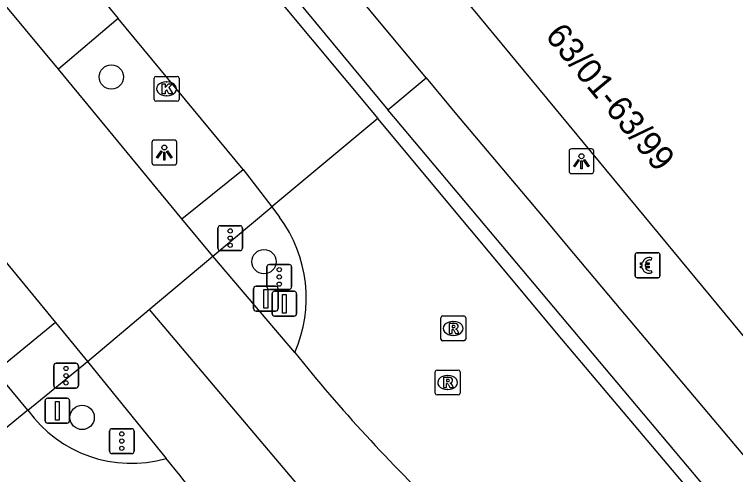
# Model space of a CAD drawing. Extents: x 159489 to 160304, y 383826 to 384530.
# Drawn here: x 160033.79 to 160062.78, y 384172.02 to 384190.51 of the extents above; entities that cross this region are included whole.
import ezdxf

# ---------------------------------------------------------------- set-up
doc = ezdxf.new("R2010")
doc.units = 0
for name, color, linetype in [('IMGEO_Berm_open', 7, 'Continuous'), ('IMGEO_Betaalautomaat', 7, 'Continuous'), ('IMGEO_Boom', 7, 'Continuous'), ('IMGEO_Fietspad_open', 7, 'Continuous'), ('IMGEO_Kolk', 7, 'Continuous'), ('IMGEO_Lichtpunt', 7, 'Continuous'), ('IMGEO_OVBaan_gesloten', 7, 'Continuous'), ('IMGEO_Pand', 7, 'Continuous'), ('IMGEO_Pand_nummerreeks', 7, 'Continuous'), ('IMGEO_Rijbaan_lokaal_gesloten', 7, 'Continuous'), ('IMGEO_Rioolput', 7, 'Continuous'), ('IMGEO_Verkeersbordpaal', 7, 'Continuous'), ('IMGEO_Verkeersregelinstallatiepaal', 7, 'Continuous'), ('IMGEO_Voetpad_open', 7, 'Continuous')]:
    doc.layers.add(name, color=color, linetype=linetype)

msp = doc.modelspace()

# ---------------------------------------------------------------- linework, layer by layer
at = {"layer": 'IMGEO_Berm_open'}
msp.add_lwpolyline([(160037.958, 384190.34), (160035.565, 384188.31)], dxfattribs=at)
at = {"layer": 'IMGEO_Betaalautomaat'}
for p, q in [((160058.815, 384180.926), (160059.656, 384180.926)), ((160059.656, 384180.926), (160058.815, 384180.926)), ((160058.74, 384180.002), (160058.74, 384180.843)), ((160058.74, 384180.843), (160058.74, 384180.002)), ((160059.402, 384180.731), (160059.385, 384180.631)), ((160059.739, 384180.852), (160059.739, 384180.011)), ((160059.739, 384180.011), (160059.739, 384180.852)), ((160059.023, 384180.39), (160059.023, 384180.458)), ((160059.144, 384180.458), (160059.144, 384180.39)), ((160059.389, 384180.225), (160059.411, 384180.138)), ((160059.665, 384179.927), (160058.824, 384179.927)), ((160058.824, 384179.927), (160059.665, 384179.927))]:
    msp.add_line(p, q, dxfattribs=at)
for points in [[(160059.023, 384180.458), (160058.954, 384180.458), (160058.954, 384180.527), (160059.033, 384180.527)], [(160059.028, 384180.321), (160058.954, 384180.321), (160058.954, 384180.39), (160059.023, 384180.39)], [(160059.155, 384180.527), (160059.302, 384180.527), (160059.302, 384180.458), (160059.144, 384180.458)], [(160059.144, 384180.39), (160059.302, 384180.39), (160059.302, 384180.321), (160059.158, 384180.321)]]:
    msp.add_lwpolyline(points, dxfattribs=at)
for centre, radius, start, end in [((160058.818, 384180.849), 0.0779, 92.4484, 184.2845), ((160058.818, 384180.849), 0.0779, 92.4484, 184.2845), ((160059.662, 384180.849), 0.0779, 2.4484, 94.2845), ((160059.662, 384180.849), 0.0779, 2.4484, 94.2845), ((160059.316, 384180.451), 0.293, 73.014, 165.0139), ((160059.322, 384180.464), 0.179, 69.3236, 159.5683), ((160059.289, 384180.376), 0.267, 191.8096, 297.0389), ((160059.322, 384180.391), 0.179, 202.7625, 291.8693), ((160058.818, 384180.005), 0.0779, 182.4484, 274.2845), ((160058.818, 384180.005), 0.0779, 182.4484, 274.2845), ((160059.662, 384180.005), 0.0779, 272.4484, 4.2845), ((160059.662, 384180.005), 0.0779, 272.4484, 4.2845)]:
    msp.add_arc(centre, radius, start, end, dxfattribs=at)
at = {"layer": 'IMGEO_Boom'}
for centre in [(160037.683, 384187.997), (160043.821, 384180.573), (160036.511, 384174.315)]:
    msp.add_circle(centre, 0.489, dxfattribs=at)
at = {"layer": 'IMGEO_Fietspad_open'}
for points in [[(160040.522, 384182.292), (160042.981, 384184.276)], [(160041.761, 384180.79), (160044.135, 384182.772)], [(160035.438, 384178.135), (160033.026, 384176.155)], [(160034.331, 384174.603), (160036.725, 384176.568)]]:
    msp.add_lwpolyline(points, dxfattribs=at)
at = {"layer": 'IMGEO_Kolk'}
for p, q in [((160039.405, 384187.093), (160039.405, 384187.945)), ((160039.48, 384188.019), (160040.332, 384188.019)), ((160040.406, 384187.945), (160040.406, 384187.093)), ((160039.893, 384187.799), (160039.918, 384187.799)), ((160040.332, 384187.019), (160039.48, 384187.019)), ((160039.916, 384187.239), (160039.891, 384187.239))]:
    msp.add_line(p, q, dxfattribs=at)
for points in [[(160039.405, 384187.093), (160039.405, 384187.945)], [(160039.48, 384188.019), (160040.332, 384188.019)], [(160040.406, 384187.945), (160040.406, 384187.093)], [(160039.726, 384187.719), (160039.849, 384187.719), (160039.849, 384187.568), (160039.979, 384187.719), (160040.143, 384187.719), (160039.997, 384187.568), (160040.15, 384187.319), (160039.998, 384187.319), (160039.913, 384187.483), (160039.849, 384187.416), (160039.849, 384187.319), (160039.726, 384187.319), (160039.726, 384187.719)], [(160040.332, 384187.019), (160039.48, 384187.019)]]:
    msp.add_lwpolyline(points, dxfattribs=at)
for centre, start, end in [((160039.482, 384187.943), 91.552, 178.448), ((160039.482, 384187.943), 91.552, 178.448), ((160040.33, 384187.943), 1.552, 88.448), ((160040.33, 384187.943), 1.552, 88.448), ((160039.482, 384187.095), 181.552, 268.448), ((160039.482, 384187.095), 181.552, 268.448), ((160040.33, 384187.095), 271.552, 358.448), ((160040.33, 384187.095), 271.552, 358.448)]:
    msp.add_arc(centre, 0.0765, start, end, dxfattribs=at)
for centre, major_axis, ratio, start_param, end_param in [((160039.892, 384187.519), (-0.387, 0.002), 0.722429, 4.712389, 7.853982), ((160039.917, 384187.519), (-0.39, 0.002), 0.717154, 1.570796, 4.712389)]:
    msp.add_ellipse(centre, major_axis=major_axis, ratio=ratio, start_param=start_param, end_param=end_param, dxfattribs=at)
at = {"layer": 'IMGEO_Lichtpunt'}
for p, q in [((160039.317, 384185.363), (160039.317, 384184.556)), ((160039.317, 384185.363), (160039.317, 384184.556)), ((160040.219, 384185.458), (160039.411, 384185.458)), ((160040.219, 384185.458), (160039.411, 384185.458)), ((160040.313, 384184.556), (160040.313, 384185.363)), ((160040.313, 384184.556), (160040.313, 384185.363)), ((160056.084, 384185.014), (160056.084, 384184.207)), ((160056.084, 384185.014), (160056.084, 384184.207)), ((160056.986, 384185.109), (160056.178, 384185.109)), ((160056.986, 384185.109), (160056.178, 384185.109)), ((160057.08, 384184.207), (160057.08, 384185.014)), ((160057.08, 384184.207), (160057.08, 384185.014)), ((160039.411, 384184.462), (160040.219, 384184.462)), ((160039.411, 384184.462), (160040.219, 384184.462)), ((160056.178, 384184.113), (160056.986, 384184.113)), ((160056.178, 384184.113), (160056.986, 384184.113))]:
    msp.add_line(p, q, dxfattribs=at)
for points in [[(160039.691, 384185.027), (160039.73, 384184.999), (160039.542, 384184.737), (160039.504, 384184.764), (160039.691, 384185.027)], [(160039.793, 384184.979), (160039.84, 384184.979), (160039.84, 384184.657), (160039.793, 384184.657), (160039.793, 384184.979)], [(160039.903, 384184.999), (160039.941, 384185.026), (160040.128, 384184.764), (160040.089, 384184.736), (160039.903, 384184.999)], [(160056.458, 384184.678), (160056.497, 384184.65), (160056.309, 384184.388), (160056.271, 384184.415), (160056.458, 384184.678)], [(160056.67, 384184.65), (160056.708, 384184.677), (160056.895, 384184.415), (160056.856, 384184.387), (160056.67, 384184.65)], [(160056.56, 384184.63), (160056.607, 384184.63), (160056.607, 384184.308), (160056.56, 384184.308), (160056.56, 384184.63)]]:
    msp.add_lwpolyline(points, dxfattribs=at)
for centre in [(160039.816, 384185.161), (160056.583, 384184.812)]:
    msp.add_circle(centre, 0.0994, dxfattribs=at)
for centre, start, end in [((160039.411, 384185.363), 90, 180), ((160039.411, 384185.363), 90, 180), ((160040.219, 384185.363), 0, 90), ((160040.219, 384185.363), 0, 90), ((160056.178, 384185.014), 90, 180), ((160056.178, 384185.014), 90, 180), ((160056.986, 384185.014), 0, 90), ((160056.986, 384185.014), 0, 90), ((160039.411, 384184.556), 180, 270), ((160039.411, 384184.556), 180, 270), ((160040.219, 384184.556), 270, 0), ((160040.219, 384184.556), 270, 360), ((160056.178, 384184.207), 180, 270), ((160056.178, 384184.207), 180, 270), ((160056.986, 384184.207), 270, 0), ((160056.986, 384184.207), 270, 360)]:
    msp.add_arc(centre, 0.0946, start, end, dxfattribs=at)
at = {"layer": 'IMGEO_OVBaan_gesloten'}
for points in [[(160035.565, 384188.31), (160015.314, 384212.637), (159985.373, 384248.854), (159983.467, 384251.216)], [(160040.522, 384182.292), (160035.565, 384188.31)], [(160030.552, 384184.07), (160035.438, 384178.135)], [(160041.761, 384180.79), (160040.522, 384182.292)], [(160039.203, 384178.646), (160041.761, 384180.79)], [(160045.06, 384176.918), (160041.761, 384180.79)], [(160036.725, 384176.568), (160039.203, 384178.646)], [(160039.203, 384178.646), (160050.903, 384164.834)], [(160035.438, 384178.135), (160036.725, 384176.568)], [(160036.725, 384176.568), (160039.888, 384172.667)]]:
    msp.add_lwpolyline(points, dxfattribs=at)
for centre, radius, start, end in [((160096.44, 384218.156), 65.882, 218.75118, 226.39396), ((159966.293, 384112.86), 94.832, 33.51445, 39.09923)]:
    msp.add_arc(centre, radius, start, end, dxfattribs=at)
at = {"layer": 'IMGEO_Pand'}
msp.add_lwpolyline([(160066.866, 384173.044), (160047.105, 384196.925), (160084.614, 384228.014), (160091.579, 384219.62), (160089.274, 384217.715), (160090.807, 384215.868), (160092.942, 384217.633), (160095.794, 384214.204), (160093.659, 384212.439), (160095.188, 384210.589), (160097.49, 384212.496), (160097.572, 384212.398), (160104.42, 384204.111), (160104.352, 384204.054)], dxfattribs=at)
at = {"layer": 'IMGEO_Rijbaan_lokaal_gesloten'}
for points in [[(159964.53, 384278.991), (160037.958, 384190.34)], [(160041.731, 384191.684), (160043.056, 384192.743), (160048.4, 384186.332)], [(160042.981, 384184.276), (160037.958, 384190.34)], [(160048.4, 384186.332), (160044.135, 384182.772)], [(160094.018, 384135.288), (160089.367, 384140.087), (160079.931, 384150.12), (160070.349, 384160.656), (160061.195, 384171.066), (160055.796, 384177.459), (160048.4, 384186.332)], [(160042.981, 384184.276), (160044.135, 384182.772)], [(160044.135, 384182.772), (160044.446, 384182.361)], [(160034.331, 384174.603), (160033.026, 384176.155)], [(160034.331, 384174.603), (160030.037, 384171.103)]]:
    msp.add_lwpolyline(points, dxfattribs=at)
for centre, radius, start, end in [((160040.06, 384179.11), 5.46, 336.3274, 36.5448), ((160038.484, 384177.582), 5.111, 215.6453, 285.9391)]:
    msp.add_arc(centre, radius, start, end, dxfattribs=at)
at = {"layer": 'IMGEO_Rioolput'}
for p, q in [((160050.928, 384177.465), (160050.928, 384178.317)), ((160051.003, 384178.391), (160051.855, 384178.391)), ((160051.929, 384178.317), (160051.929, 384177.465)), ((160051.416, 384178.171), (160051.441, 384178.171)), ((160051.439, 384177.611), (160051.414, 384177.611)), ((160051.855, 384177.391), (160051.003, 384177.391)), ((160050.703, 384175.291), (160050.703, 384176.143)), ((160050.778, 384176.217), (160051.63, 384176.217)), ((160051.191, 384175.997), (160051.216, 384175.997)), ((160051.704, 384176.143), (160051.704, 384175.291)), ((160051.214, 384175.437), (160051.189, 384175.437)), ((160051.63, 384175.217), (160050.778, 384175.217))]:
    msp.add_line(p, q, dxfattribs=at)
for points in [[(160050.928, 384177.465), (160050.928, 384178.317)], [(160051.003, 384178.391), (160051.855, 384178.391)], [(160051.929, 384178.317), (160051.929, 384177.465)], [(160051.517, 384178.089), (160051.265, 384178.091), (160051.265, 384177.691)], [(160051.443, 384178.01), (160051.389, 384178.01), (160051.389, 384177.929)], [(160051.265, 384177.691), (160051.389, 384177.691), (160051.389, 384177.853), (160051.4, 384177.853)], [(160051.389, 384177.929), (160051.441, 384177.929)], [(160051.447, 384177.824), (160051.518, 384177.691), (160051.658, 384177.691), (160051.593, 384177.817)], [(160051.855, 384177.391), (160051.003, 384177.391)], [(160050.703, 384175.291), (160050.703, 384176.143)], [(160050.778, 384176.217), (160051.63, 384176.217)], [(160051.704, 384176.143), (160051.704, 384175.291)], [(160051.292, 384175.915), (160051.04, 384175.917), (160051.04, 384175.517)], [(160051.218, 384175.836), (160051.164, 384175.836), (160051.164, 384175.755)], [(160051.164, 384175.755), (160051.216, 384175.755)], [(160051.04, 384175.517), (160051.164, 384175.517), (160051.164, 384175.679), (160051.175, 384175.679)], [(160051.222, 384175.65), (160051.293, 384175.517), (160051.433, 384175.517), (160051.368, 384175.643)], [(160051.63, 384175.217), (160050.778, 384175.217)]]:
    msp.add_lwpolyline(points, dxfattribs=at)
for centre, radius, start, end in [((160051.005, 384178.315), 0.0765, 91.552, 178.448), ((160051.005, 384178.315), 0.0765, 91.552, 178.448), ((160051.853, 384178.315), 0.0765, 1.552, 88.448), ((160051.853, 384178.315), 0.0765, 1.552, 88.448), ((160051.449, 384177.914), 0.0964, 77.0061, 93.1865), ((160051.463, 384177.971), 0.0378, 276.6634, 79.6772), ((160051.516, 384177.979), 0.109, 350.3612, 89.416), ((160051.399, 384177.8), 0.0533, 26.0293, 88.6989), ((160051.425, 384178.118), 0.19, 274.7715, 282.9687), ((160051.514, 384177.979), 0.112, 277.5842, 350.9817), ((160051.498, 384177.764), 0.108, 29.5134, 73.7905), ((160051.005, 384177.467), 0.0765, 181.552, 268.448), ((160051.005, 384177.467), 0.0765, 181.552, 268.448), ((160051.853, 384177.467), 0.0765, 271.552, 358.448), ((160051.853, 384177.467), 0.0765, 271.552, 358.448), ((160050.78, 384176.141), 0.0765, 91.552, 178.448), ((160050.78, 384176.141), 0.0765, 91.552, 178.448), ((160051.628, 384176.141), 0.0765, 1.552, 88.448), ((160051.628, 384176.141), 0.0765, 1.552, 88.448), ((160051.2, 384175.944), 0.19, 274.7715, 282.9687), ((160051.224, 384175.74), 0.0964, 77.0061, 93.1865), ((160051.238, 384175.797), 0.0378, 276.6634, 79.6772), ((160051.291, 384175.805), 0.109, 350.3612, 89.416), ((160051.289, 384175.805), 0.112, 277.5842, 350.9817), ((160051.273, 384175.59), 0.108, 29.5134, 73.7905), ((160051.174, 384175.626), 0.0533, 26.0293, 88.6989), ((160050.78, 384175.293), 0.0765, 181.552, 268.448), ((160050.78, 384175.293), 0.0765, 181.552, 268.448), ((160051.628, 384175.293), 0.0765, 271.552, 358.448), ((160051.628, 384175.293), 0.0765, 271.552, 358.448)]:
    msp.add_arc(centre, radius, start, end, dxfattribs=at)
for centre, major_axis, ratio, start_param, end_param in [((160051.415, 384177.891), (-0.387, 0.002), 0.722429, 4.712389, 7.853982), ((160051.44, 384177.891), (-0.39, 0.002), 0.717154, 1.570796, 4.712389), ((160051.19, 384175.717), (-0.387, 0.002), 0.722429, 4.712389, 7.853982), ((160051.215, 384175.717), (-0.39, 0.002), 0.717154, 1.570796, 4.712389)]:
    msp.add_ellipse(centre, major_axis=major_axis, ratio=ratio, start_param=start_param, end_param=end_param, dxfattribs=at)
at = {"layer": 'IMGEO_Verkeersbordpaal'}
for p, q in [((160043.4, 384178.687), (160043.4, 384179.487)), ((160043.4, 384179.487), (160043.4, 384178.687)), ((160043.5, 384179.587), (160044.29, 384179.587)), ((160044.29, 384179.587), (160043.5, 384179.587)), ((160044.39, 384179.487), (160044.39, 384178.687)), ((160044.39, 384178.687), (160044.39, 384179.487)), ((160044.144, 384178.484), (160044.144, 384179.284)), ((160044.144, 384179.284), (160044.144, 384178.484)), ((160044.244, 384179.384), (160045.034, 384179.384)), ((160045.034, 384179.384), (160044.244, 384179.384)), ((160045.134, 384179.284), (160045.134, 384178.484)), ((160045.134, 384178.484), (160045.134, 384179.284)), ((160044.29, 384178.587), (160043.5, 384178.587)), ((160043.5, 384178.587), (160044.29, 384178.587)), ((160045.034, 384178.384), (160044.244, 384178.384)), ((160044.244, 384178.384), (160045.034, 384178.384)), ((160035.019, 384174.184), (160035.019, 384174.984)), ((160035.019, 384174.984), (160035.019, 384174.184)), ((160035.119, 384175.084), (160035.909, 384175.084)), ((160035.909, 384175.084), (160035.119, 384175.084)), ((160036.009, 384174.984), (160036.009, 384174.184)), ((160036.009, 384174.184), (160036.009, 384174.984)), ((160035.909, 384174.084), (160035.119, 384174.084)), ((160035.119, 384174.084), (160035.909, 384174.084))]:
    msp.add_line(p, q, dxfattribs=at)
for points in [[(160043.82, 384179.462), (160043.97, 384179.462), (160043.97, 384178.712), (160043.82, 384178.712), (160043.82, 384179.462)], [(160044.564, 384179.259), (160044.714, 384179.259), (160044.714, 384178.509), (160044.564, 384178.509), (160044.564, 384179.259)], [(160035.439, 384174.959), (160035.589, 384174.959), (160035.589, 384174.209), (160035.439, 384174.209), (160035.439, 384174.959)]]:
    msp.add_lwpolyline(points, dxfattribs=at)
for centre, start, end in [((160043.5, 384179.487), 90, 180), ((160043.5, 384179.487), 90, 180), ((160044.29, 384179.487), 0, 90), ((160044.29, 384179.487), 360, 90), ((160044.244, 384179.284), 90, 180), ((160044.244, 384179.284), 90, 180), ((160045.034, 384179.284), 0, 90), ((160045.034, 384179.284), 360, 90), ((160043.5, 384178.687), 180, 270), ((160043.5, 384178.687), 180, 270), ((160044.29, 384178.687), 270, 0), ((160044.29, 384178.687), 270, 0), ((160044.244, 384178.484), 180, 270), ((160044.244, 384178.484), 180, 270), ((160045.034, 384178.484), 270, 0), ((160045.034, 384178.484), 270, 0), ((160035.119, 384174.984), 90, 180), ((160035.119, 384174.984), 90, 180), ((160035.909, 384174.984), 0, 90), ((160035.909, 384174.984), 360, 90), ((160035.119, 384174.184), 180, 270), ((160035.119, 384174.184), 180, 270), ((160035.909, 384174.184), 270, 0), ((160035.909, 384174.184), 270, 0)]:
    msp.add_arc(centre, 0.1, start, end, dxfattribs=at)
at = {"layer": 'IMGEO_Verkeersregelinstallatiepaal'}
for p, q in [((160041.968, 384181.119), (160041.968, 384181.919)), ((160041.968, 384181.919), (160041.968, 384181.119)), ((160042.068, 384182.019), (160042.858, 384182.019)), ((160042.858, 384182.019), (160042.068, 384182.019)), ((160042.958, 384181.919), (160042.958, 384181.119)), ((160042.958, 384181.119), (160042.958, 384181.919)), ((160042.858, 384181.019), (160042.068, 384181.019)), ((160042.068, 384181.019), (160042.858, 384181.019)), ((160043.939, 384179.561), (160043.939, 384180.361)), ((160043.939, 384180.361), (160043.939, 384179.561)), ((160044.039, 384180.461), (160044.829, 384180.461)), ((160044.829, 384180.461), (160044.039, 384180.461)), ((160044.929, 384180.361), (160044.929, 384179.561)), ((160044.929, 384179.561), (160044.929, 384180.361)), ((160044.829, 384179.461), (160044.039, 384179.461)), ((160044.039, 384179.461), (160044.829, 384179.461)), ((160035.369, 384175.592), (160035.369, 384176.392)), ((160035.369, 384176.392), (160035.369, 384175.592)), ((160035.469, 384176.492), (160036.259, 384176.492)), ((160036.259, 384176.492), (160035.469, 384176.492)), ((160036.359, 384176.392), (160036.359, 384175.592)), ((160036.359, 384175.592), (160036.359, 384176.392)), ((160036.259, 384175.492), (160035.469, 384175.492)), ((160035.469, 384175.492), (160036.259, 384175.492)), ((160037.61, 384172.963), (160037.61, 384173.763)), ((160037.61, 384173.763), (160037.61, 384172.963)), ((160037.71, 384173.863), (160038.5, 384173.863)), ((160038.5, 384173.863), (160037.71, 384173.863)), ((160038.6, 384173.763), (160038.6, 384172.963)), ((160038.6, 384172.963), (160038.6, 384173.763)), ((160038.5, 384172.863), (160037.71, 384172.863)), ((160037.71, 384172.863), (160038.5, 384172.863))]:
    msp.add_line(p, q, dxfattribs=at)
for centre in [(160042.463, 384181.809), (160042.463, 384181.519), (160042.463, 384181.229), (160044.434, 384180.251), (160044.434, 384179.961), (160044.434, 384179.671), (160035.864, 384176.282), (160035.864, 384175.992), (160035.864, 384175.702), (160038.105, 384173.653), (160038.105, 384173.363), (160038.105, 384173.073)]:
    msp.add_circle(centre, 0.085, dxfattribs=at)
for centre, start, end in [((160042.068, 384181.919), 90, 180), ((160042.068, 384181.919), 90, 180), ((160042.858, 384181.919), 0, 90), ((160042.858, 384181.919), 360, 90), ((160042.068, 384181.119), 180, 270), ((160042.068, 384181.119), 180, 270), ((160042.858, 384181.119), 270, 0), ((160042.858, 384181.119), 270, 0), ((160044.039, 384180.361), 90, 180), ((160044.039, 384180.361), 90, 180), ((160044.829, 384180.361), 0, 90), ((160044.829, 384180.361), 360, 90), ((160044.039, 384179.561), 180, 270), ((160044.039, 384179.561), 180, 270), ((160044.829, 384179.561), 270, 0), ((160044.829, 384179.561), 270, 0), ((160035.469, 384176.392), 90, 180), ((160035.469, 384176.392), 90, 180), ((160036.259, 384176.392), 0, 90), ((160036.259, 384176.392), 360, 90), ((160035.469, 384175.592), 180, 270), ((160035.469, 384175.592), 180, 270), ((160036.259, 384175.592), 270, 0), ((160036.259, 384175.592), 270, 0), ((160037.71, 384173.763), 90, 180), ((160037.71, 384173.763), 90, 180), ((160038.5, 384173.763), 0, 90), ((160038.5, 384173.763), 360, 90), ((160037.71, 384172.963), 180, 270), ((160037.71, 384172.963), 180, 270), ((160038.5, 384172.963), 270, 0), ((160038.5, 384172.963), 270, 0)]:
    msp.add_arc(centre, 0.1, start, end, dxfattribs=at)
at = {"layer": 'IMGEO_Voetpad_open'}
for points in [[(159937.427, 384324.203), (159935.905, 384322.929), (160048.804, 384186.671)], [(160050.34, 384187.958), (160045.884, 384193.335), (160045.088, 384194.296), (160035.789, 384205.516), (160035.01, 384206.456), (159975.49, 384278.275)], [(160048.804, 384186.671), (160050.34, 384187.958)], [(160050.34, 384187.958), (160051.553, 384186.494), (160055.185, 384182.183), (160055.979, 384181.24), (160057.954, 384178.895), (160063.061, 384172.832), (160065.382, 384170.193), (160066.214, 384169.246), (160072.272, 384162.355), (160075.872, 384158.402), (160076.696, 384157.497), (160082.448, 384151.179), (160091.223, 384141.843), (160105.53, 384127.244), (160129.28, 384103.698), (160141.431, 384091.785), (160146.087, 384087.221), (160154.183, 384079.487), (160154.902, 384078.8), (160161.156, 384072.825), (160168.424, 384066.164), (160174.496, 384060.831), (160173.165, 384059.326)], [(160173.165, 384059.326), (160167.091, 384064.648), (160161.015, 384070.183), (160146.171, 384084.356), (160127.88, 384102.246), (160104.079, 384125.847), (160094.817, 384135.246), (160084.845, 384145.686), (160074.003, 384157.433), (160066.213, 384166.161), (160061.626, 384171.427), (160049.101, 384186.313), (160048.804, 384186.671)]]:
    msp.add_lwpolyline(points, dxfattribs=at)

# ---------------------------------------------------------------- texts
at = {"layer": 'IMGEO_Pand_nummerreeks'}
msp.add_text('63/01-63/99', height=1, rotation=309.6084, dxfattribs=at).set_placement((160055.089, 384189.63))

doc.saveas('drawing.dxf')
